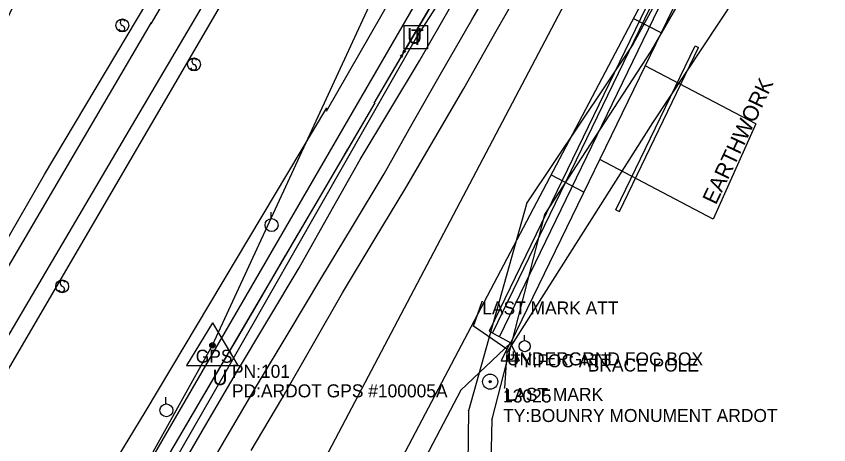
# Model space of a CAD drawing. Extents: x 978516 to 993312, y 1836504 to 1846212.
# Drawn here: x 981200.4 to 981512.6, y 1841277.7 to 1841442.4 of the extents above; entities that cross this region are included whole.
import ezdxf

# ---------------------------------------------------------------- set-up
doc = ezdxf.new("R2010")
doc.units = 0
for name, color, linetype in [('Default', 7, 'Continuous'), ('R_Drainage', 7, 'Continuous'), ('R_MOT Stage 1 Widening', 7, 'Continuous'), ('R_Proposed Road', 7, 'Continuous'), ('S_BASELINE', 7, 'Continuous'), ('S_EDGE_PAVEMENT', 7, 'Continuous'), ('S_FENCE', 7, 'Continuous'), ('S_FIBER_OPTIC_CABLE', 7, 'Continuous'), ('S_FIBER_OPTIC_CABLE_ANNOT', 7, 'Continuous'), ('S_GAS_UTILITIES', 7, 'Continuous'), ('S_IRON_PIN', 7, 'Continuous'), ('S_IRON_PIN_ANNOT', 7, 'Continuous'), ('S_MISC_BOUNDARY_ANNOT', 7, 'Continuous'), ('S_MISC_STRUCTURES_ANNOT', 7, 'Continuous'), ('S_PAVEMENT_CROWN', 7, 'Continuous'), ('S_PRIMARY_CTL', 7, 'Continuous'), ('S_PRIMARY_CTL_ANNOT', 7, 'Continuous'), ('S_SANITARY_SEWER', 7, 'Continuous'), ('S_SHOULDER', 7, 'Continuous'), ('S_SIGN', 7, 'Continuous'), ('S_STREAM', 7, 'Continuous'), ('S_TELEPHONE_UTILITIES', 7, 'Continuous'), ('S_UNDERGROUND_CABLE', 7, 'Continuous'), ('S_UTILITY_POLE', 7, 'Continuous'), ('S_UTILITY_POLE_ANNOT', 7, 'Continuous'), ('S_UTL_PT_SYM', 7, 'Continuous'), ('S_WATER_UTILITIES', 7, 'Continuous')]:
    doc.layers.add(name, color=color, linetype=linetype)

msp = doc.modelspace()

# ---------------------------------------------------------------- linework, layer by layer
at = {"layer": 'R_Drainage'}
for p, q in [((981430.84, 1841368.02), (981461.27, 1841431.06)), ((981432.19, 1841367.36), (981462.62, 1841430.4)), ((981461.27, 1841431.06), (981462.62, 1841430.4)), ((981430.84, 1841368.02), (981432.19, 1841367.36))]:
    msp.add_line(p, q, dxfattribs=at)
at = {"layer": 'R_MOT Stage 1 Widening'}
msp.add_line((981449.82, 1841520.69), (980710.25, 1840116.94), dxfattribs=at)
at = {"layer": 'R_Proposed Road'}
for p, q in [((981472.82, 1841508.57), (980733.25, 1840104.82)), ((981472.82, 1841508.57), (981382.06, 1841321.29)), ((981383.39, 1841320.59), (981474.15, 1841507.87)), ((981386.04, 1841319.19), (981476.8, 1841506.47)), ((981390.47, 1841316.86), (981481.23, 1841504.14)), ((981448.19, 1841435.98), (981437.53, 1841441.59)), ((981484.58, 1841400.98), (981442.08, 1841423.37)), ((981484.58, 1841400.99), (981468.17, 1841364.42)), ((981468.17, 1841364.42), (981424.63, 1841387.36)), ((981418.52, 1841374.75), (981405.84, 1841381.43)), ((981382.06, 1841321.29), (981390.47, 1841316.86)), ((981390.47, 1841316.86), (981371.29, 1841298.7)), ((981371.29, 1841298.7), (980740.33, 1840101.09))]:
    msp.add_line(p, q, dxfattribs=at)
at = {"layer": 'S_BASELINE'}
for p, q in [((981275.76, 1841315.9), (981527.92, 1841862.16)), ((980929, 1840693.9), (981275.76, 1841315.9))]:
    msp.add_line(p, q, dxfattribs=at)
at = {"layer": 'S_EDGE_PAVEMENT'}
for points in [[(981261.53, 1841265.2), (981273.27, 1841285.32), (981285.01, 1841305.43), (981297.05, 1841325.55), (981309.09, 1841345.67), (981320.79, 1841366.5), (981332.48, 1841387.33), (981343.88, 1841406.29), (981355.28, 1841425.25), (981367.24, 1841446.01), (981379.2, 1841466.76), (981391.14, 1841487.35), (981403.07, 1841507.93), (981414.3, 1841526.71), (981425.54, 1841545.48), (981438.09, 1841566.9), (981450.64, 1841588.31), (981462.61, 1841607.97), (981474.58, 1841627.63), (981486.64, 1841648.11), (981498.7, 1841668.6), (981509.5, 1841686.69)], [(981290.58, 1841275.5), (981302.42, 1841295.38), (981314.11, 1841315.75), (981325.8, 1841336.12), (981337.98, 1841356.27), (981350.15, 1841376.43), (981361.23, 1841395.55), (981372.32, 1841414.67), (981384.31, 1841435.76), (981396.3, 1841456.85), (981407.72, 1841477.21), (981419.13, 1841497.58), (981431.13, 1841516.92), (981443.13, 1841536.27), (981455.15, 1841556.64), (981467.17, 1841577.02), (981479, 1841597.77), (981490.83, 1841618.53), (981503.2, 1841638.52), (981515.58, 1841658.52)], [(981326.16, 1841566.09), (981325.3, 1841564.63), (981252.14, 1841439.54)], [(981252.24, 1841439.93), (981137.33, 1841244.03), (981073.65, 1841136.11), (981002.81, 1841014.58), (980948.5, 1840922.78), (980947.47, 1840923.27), (981050.93, 1841147.81), (981148.36, 1841360.38), (981201.55, 1841475.56)], [(980851.24, 1840712.34), (980867.77, 1840746.22), (980923.19, 1840850.45), (980998.48, 1840980.73), (981063.54, 1841091.76), (981158.12, 1841253.15), (981246.33, 1841402.78), (981273.99, 1841449.85)]]:
    msp.add_lwpolyline(points, dxfattribs=at)
at = {"layer": 'S_FENCE'}
for p, q in [((981347.91, 1841426.99), (981350.1, 1841429)), ((981348.64, 1841426.53), (981349.37, 1841429.46)), ((981327.77, 1841391.35), (981326.24, 1841388.84)), ((981327.69, 1841391.31), (981326.32, 1841388.87)), ((981305.53, 1841353.38), (981304.01, 1841350.87)), ((981305.46, 1841353.34), (981304.08, 1841350.9)), ((981283.3, 1841315.41), (981281.78, 1841312.9)), ((981283.23, 1841315.37), (981281.85, 1841312.94))]:
    msp.add_line(p, q, dxfattribs=at)
for points in [[(981337.87, 1841409.02), (981427.3, 1841561.4), (981523.23, 1841724.55), (981572.79, 1841807.12), (981680.85, 1841992.62)], [(981350.02, 1841429.72), (981360.14, 1841446.97)], [(981337.87, 1841409.02), (981347.99, 1841426.27)], [(981338.12, 1841409.07), (981210.88, 1841191.78), (981153.76, 1841094.26)], [(981338.12, 1841409.07), (981328.02, 1841391.82)], [(981325.99, 1841388.36), (981315.89, 1841371.11)], [(981315.89, 1841371.11), (981305.78, 1841353.85)], [(981303.76, 1841350.4), (981293.66, 1841333.14)], [(981293.66, 1841333.14), (981283.55, 1841315.88)], [(981281.53, 1841312.43), (981271.42, 1841295.17)], [(981271.42, 1841295.17), (981261.32, 1841277.91)]]:
    msp.add_lwpolyline(points, dxfattribs=at)
at = {"layer": 'S_FIBER_OPTIC_CABLE'}
for p, q in [((981489.76, 1841469.15), (981444.84, 1841401.42)), ((981444.84, 1841401.42), (981388.93, 1841313.19)), ((981376.11, 1841323.22), (981379.45, 1841332.76)), ((981388.87, 1841314.36), (981376.11, 1841323.22)), ((981388.93, 1841313.19), (981388.03, 1841299.54)), ((981279.43, 1841303.14), (981234.38, 1841225.12))]:
    msp.add_line(p, q, dxfattribs=at)
at = {"layer": 'S_GAS_UTILITIES'}
for p, q in [((981481.74, 1841494.4), (981444.26, 1841428.97)), ((981444.26, 1841428.97), (981403.43, 1841366.18)), ((981403.43, 1841366.18), (981383.19, 1841287.56)), ((981383.19, 1841287.56), (981380.96, 1841208.13))]:
    msp.add_line(p, q, dxfattribs=at)
at = {"layer": 'S_IRON_PIN'}
for radius in [2.91, 0.411, 0.262, 0.212, 0.145, 0.0822, 0.0581]:
    msp.add_circle((981382.48, 1841301.92), radius, dxfattribs=at)
at = {"layer": 'S_PAVEMENT_CROWN'}
msp.add_lwpolyline([(981269.82, 1841261), (981281.47, 1841280.93), (981293.13, 1841300.86), (981305.25, 1841321.13), (981317.37, 1841341.4), (981329.54, 1841361.63), (981341.72, 1841381.86), (981352.54, 1841400.98), (981363.36, 1841420.11), (981375.51, 1841441.02), (981387.66, 1841461.92), (981399.38, 1841482.34), (981411.1, 1841502.76), (981422.77, 1841521.87), (981434.43, 1841540.97), (981446.93, 1841561.93), (981459.42, 1841582.88), (981471.44, 1841603.03), (981483.47, 1841623.17), (981495.31, 1841643.33), (981507.15, 1841663.48), (981518.44, 1841681.75)], dxfattribs=at)
at = {"layer": 'S_PRIMARY_CTL'}
for p, q in [((981275.76, 1841324.6), (981265.73, 1841308.08)), ((981275.76, 1841324.6), (981285.58, 1841308.08)), ((981265.73, 1841308.08), (981285.58, 1841308.08))]:
    msp.add_line(p, q, dxfattribs=at)
for radius in [1.04, 0.609, 0.344]:
    msp.add_circle((981275.76, 1841315.9), radius, dxfattribs=at)
at = {"layer": 'S_SANITARY_SEWER'}
msp.add_line((981356.68, 1841452.4), (981249.63, 1841267.79), dxfattribs=at)
at = {"layer": 'S_SHOULDER'}
for points in [[(981211.39, 1841472.61), (981158.31, 1841358.64), (981093.64, 1841217.39), (981057.34, 1841136.93), (981051.73, 1841125.11), (981059.01, 1841122.03), (981063.26, 1841125.91), (981127.73, 1841236.45), (981211.26, 1841381.53), (981258.43, 1841461.01)], [(981279.6, 1841447.92), (981085.77, 1841115.96), (980988.34, 1840949.05), (980938.02, 1840861.46), (980902.15, 1840792.78), (980878.86, 1840748.32)]]:
    msp.add_lwpolyline(points, dxfattribs=at)
at = {"layer": 'S_SIGN'}
for centre in [(981241.13, 1841438.85), (981268.68, 1841423.87), (981218, 1841338.57)]:
    msp.add_circle(centre, 2.49, dxfattribs=at)
for centre, radius, start, end in [((981241.82, 1841440.17), 1.5, 167.1196, 241.9813), ((981241.2, 1841440.11), 0.95, 16.5258, 156.8957), ((981240.98, 1841438.02), 1.28, 204.641, 335.359), ((981240.72, 1841437.5), 1.4, 358.6529, 73.7063), ((981269.37, 1841425.19), 1.5, 167.1196, 241.9813), ((981268.76, 1841425.14), 0.95, 16.5258, 156.8957), ((981268.27, 1841422.53), 1.4, 358.6529, 73.7063), ((981268.53, 1841423.04), 1.28, 204.641, 335.359), ((981218.69, 1841339.9), 1.5, 167.1196, 241.9813), ((981218.08, 1841339.84), 0.95, 16.5258, 156.8957), ((981217.85, 1841337.75), 1.28, 204.641, 335.359), ((981217.59, 1841337.23), 1.4, 358.6529, 73.7063)]:
    msp.add_arc(centre, radius, start, end, dxfattribs=at)
at = {"layer": 'S_STREAM'}
for points in [[(981412.53, 1841563.18), (981357.3, 1841471.83), (981319.43, 1841405.83)], [(981319.62, 1841407.18), (981249.81, 1841290.16), (981184.15, 1841182.48), (981115.27, 1841064.44), (981067.01, 1840985.7), (981039.67, 1840945.24), (981032.53, 1840935.58), (981031.46, 1840933.32), (981012.51, 1840898.35), (980966.65, 1840813.92), (980919.78, 1840726.69)]]:
    msp.add_lwpolyline(points, dxfattribs=at)
at = {"layer": 'S_TELEPHONE_UTILITIES'}
msp.add_lwpolyline([(981349.48, 1841429.89), (981349.48, 1841438.89), (981358.48, 1841438.89), (981358.48, 1841429.89)], close=True, dxfattribs=at)
at = {"layer": 'S_UNDERGROUND_CABLE'}
for p, q in [((981384.36, 1841481.78), (981354.21, 1841434.41)), ((981354.21, 1841434.41), (981279.43, 1841303.14)), ((981390.2, 1841316.99), (981386.68, 1841309.9)), ((981390.2, 1841316.99), (981393.69, 1841309.9)), ((981389, 1841311.14), (981389, 1841313.58)), ((981389.62, 1841310.48), (981389, 1841311.14)), ((981391.36, 1841311.14), (981390.82, 1841310.48)), ((981391.36, 1841313.58), (981391.36, 1841311.14)), ((981386.68, 1841309.9), (981393.69, 1841309.9)), ((981390.82, 1841310.48), (981389.62, 1841310.48))]:
    msp.add_line(p, q, dxfattribs=at)
at = {"layer": 'S_UTILITY_POLE'}
for p, q in [((981298.34, 1841364.65), (981298.34, 1841367.13)), ((981395.64, 1841317.71), (981395.64, 1841319.82)), ((981257.9, 1841293.43), (981257.9, 1841295.91))]:
    msp.add_line(p, q, dxfattribs=at)
for centre, radius in [((981298.48, 1841362.13), 2.5), ((981395.77, 1841315.57), 2.13), ((981258.04, 1841290.91), 2.5)]:
    msp.add_circle(centre, radius, dxfattribs=at)
at = {"layer": 'S_UTL_PT_SYM'}
for points in [[(981354.21, 1841434.41), (981354.21, 1841434.46), (981354.21, 1841434.41), (981354.16, 1841434.41), (981354.21, 1841434.41), (981354.21, 1841434.36), (981354.21, 1841434.41), (981354.26, 1841434.41)], [(981437.32, 1841431.56), (981437.32, 1841431.61), (981437.32, 1841431.56), (981437.27, 1841431.56), (981437.32, 1841431.56), (981437.32, 1841431.51), (981437.32, 1841431.56), (981437.37, 1841431.56)], [(981444.26, 1841428.97), (981444.26, 1841429.02), (981444.26, 1841428.97), (981444.21, 1841428.97), (981444.26, 1841428.97), (981444.26, 1841428.92), (981444.26, 1841428.97), (981444.31, 1841428.97)], [(981444.84, 1841401.42), (981444.84, 1841401.47), (981444.84, 1841401.42), (981444.79, 1841401.42), (981444.84, 1841401.42), (981444.84, 1841401.37), (981444.84, 1841401.42), (981444.89, 1841401.42)], [(981396.62, 1841370.63), (981396.62, 1841370.68), (981396.62, 1841370.63), (981396.57, 1841370.63), (981396.62, 1841370.63), (981396.62, 1841370.58), (981396.62, 1841370.63), (981396.67, 1841370.63)], [(981403.43, 1841366.18), (981403.43, 1841366.23), (981403.43, 1841366.18), (981403.38, 1841366.18), (981403.43, 1841366.18), (981403.43, 1841366.13), (981403.43, 1841366.18), (981403.48, 1841366.18)], [(981379.45, 1841332.76), (981379.45, 1841332.81), (981379.45, 1841332.76), (981379.4, 1841332.76), (981379.45, 1841332.76), (981379.45, 1841332.71), (981379.45, 1841332.76), (981379.5, 1841332.76)], [(981376.11, 1841323.22), (981376.11, 1841323.27), (981376.11, 1841323.22), (981376.06, 1841323.22), (981376.11, 1841323.22), (981376.11, 1841323.17), (981376.11, 1841323.22), (981376.16, 1841323.22)], [(981388.87, 1841314.36), (981388.87, 1841314.41), (981388.87, 1841314.36), (981388.82, 1841314.36), (981388.87, 1841314.36), (981388.87, 1841314.31), (981388.87, 1841314.36), (981388.92, 1841314.36)], [(981388.93, 1841313.19), (981388.93, 1841313.24), (981388.93, 1841313.19), (981388.88, 1841313.19), (981388.93, 1841313.19), (981388.93, 1841313.14), (981388.93, 1841313.19), (981388.98, 1841313.19)], [(981279.43, 1841303.14), (981279.43, 1841303.19), (981279.43, 1841303.14), (981279.38, 1841303.14), (981279.43, 1841303.14), (981279.43, 1841303.09), (981279.43, 1841303.14), (981279.48, 1841303.14)], [(981388.03, 1841299.54), (981388.03, 1841299.59), (981388.03, 1841299.54), (981387.98, 1841299.54), (981388.03, 1841299.54), (981388.03, 1841299.49), (981388.03, 1841299.54), (981388.08, 1841299.54)], [(981374.19, 1841290.76), (981374.19, 1841290.81), (981374.19, 1841290.76), (981374.14, 1841290.76), (981374.19, 1841290.76), (981374.19, 1841290.71), (981374.19, 1841290.76), (981374.24, 1841290.76)], [(981383.19, 1841287.56), (981383.19, 1841287.61), (981383.19, 1841287.56), (981383.14, 1841287.56), (981383.19, 1841287.56), (981383.19, 1841287.51), (981383.19, 1841287.56), (981383.24, 1841287.56)]]:
    msp.add_lwpolyline(points, dxfattribs=at)
at = {"layer": 'S_WATER_UTILITIES'}
for p, q in [((981472.27, 1841495.53), (981437.32, 1841431.56)), ((981437.32, 1841431.56), (981396.62, 1841370.63)), ((981396.62, 1841370.63), (981374.19, 1841290.76)), ((981374.19, 1841290.76), (981373.18, 1841207.51))]:
    msp.add_line(p, q, dxfattribs=at)

# ---------------------------------------------------------------- texts
at = {"layer": 'Default'}
for p in [(981350.58, 1841431.86), (981275.8, 1841300.59)]:
    msp.add_text('U', height=6, dxfattribs=at).set_placement(p)
at = {"layer": 'S_FIBER_OPTIC_CABLE_ANNOT'}
for s, p in [('LAST MARK ATT', (981379.45, 1841327.76)), ('LAST MARK', (981388.03, 1841294.54))]:
    msp.add_text(s, height=5, dxfattribs=at).set_placement(p)
at = {"layer": 'S_IRON_PIN_ANNOT'}
for s, p in [('13025', (981387.48, 1841293.92)), ('TY:BOUNRY MONUMENT ARDOT', (981387.48, 1841286.42))]:
    msp.add_text(s, height=5, dxfattribs=at).set_placement(p)
at = {"layer": 'S_MISC_BOUNDARY_ANNOT'}
msp.add_text('EARTHWORK', height=6.001, rotation=64.6953, dxfattribs=at).set_placement((981469.26, 1841369.62))
at = {"layer": 'S_MISC_STRUCTURES_ANNOT'}
for s, p in [('UNDERGRND FOC BOX', (981388.93, 1841308.19)), ('BRACE POLE', (981420.02, 1841305.82))]:
    msp.add_text(s, height=5, dxfattribs=at).set_placement(p)
at = {"layer": 'S_PRIMARY_CTL'}
msp.add_text('GPS', height=5, dxfattribs=at).set_placement((981269.32, 1841309.19))
at = {"layer": 'S_PRIMARY_CTL_ANNOT'}
for s, p in [('PN:101', (981283.26, 1841303.4)), ('PD:ARDOT GPS #100005A', (981283.26, 1841295.9))]:
    msp.add_text(s, height=5, dxfattribs=at).set_placement(p)
at = {"layer": 'S_TELEPHONE_UTILITIES'}
msp.add_text('T', height=6, dxfattribs=at).set_placement((981352.04, 1841431.39))
at = {"layer": 'S_UTILITY_POLE_ANNOT'}
msp.add_text('TY:FOC ATT', height=5, dxfattribs=at).set_placement((981390.2, 1841307.46))

doc.saveas('drawing.dxf')
